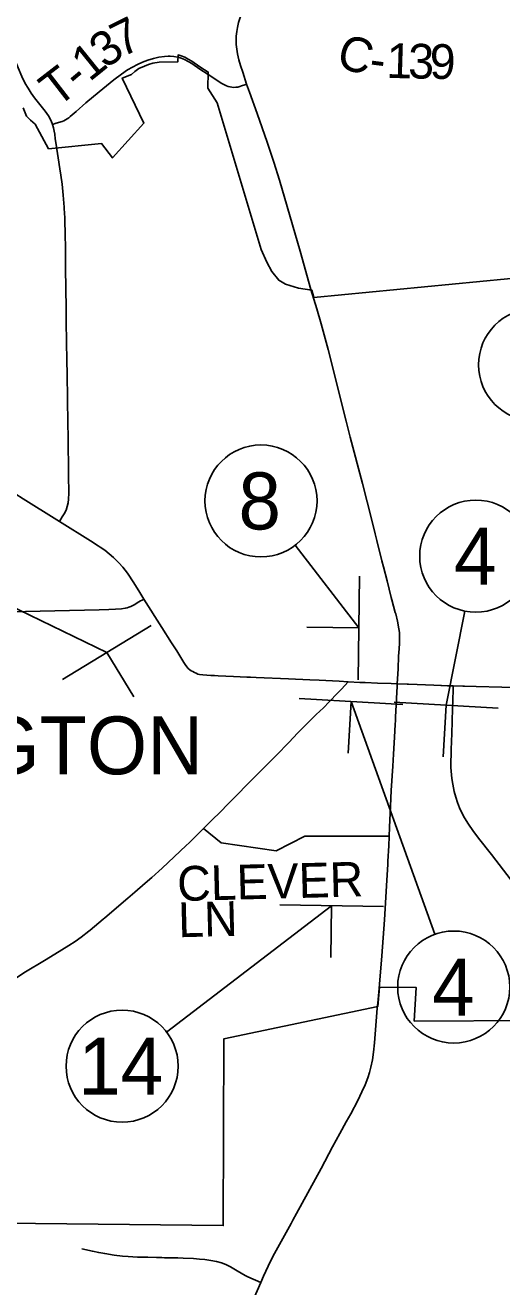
# Model space of a CAD drawing. Extents: x 40529 to 41139, y 15164 to 15584.
# Drawn here: x 40574.5 to 40597.9, y 15483.8 to 15545.7 of the extents above; entities that cross this region are included whole.
import ezdxf

# ---------------------------------------------------------------- set-up
doc = ezdxf.new("R2010")
doc.units = 0
for name, color, linetype in [('Default', 7, 'Continuous'), ('GM_X_Corporation', 7, 'Continuous'), ('GM_X_Corporation_Text', 7, 'Continuous'), ('GM_X_County_Road', 7, 'Continuous'), ('GM_X_County_Road_Text', 7, 'Continuous'), ('GM_X_State_Route', 7, 'Continuous'), ('GM_X_Township_Road', 7, 'Continuous'), ('GM_X_Township_Road_Text', 7, 'Continuous'), ('GM_X_US_Route', 7, 'Continuous'), ('SH_Data', 7, 'Continuous'), ('SH_Text', 7, 'Continuous')]:
    doc.layers.add(name, color=color, linetype=linetype)

msp = doc.modelspace()

# ---------------------------------------------------------------- linework, layer by layer
at = {"layer": 'Default'}
for p, q in [((40590.846, 15513.587), (40590.911, 15518.682)), ((40580.694, 15516.247), (40576.336, 15513.605)), ((40590.878, 15516.135), (40588.331, 15516.167)), ((40578.515, 15514.926), (40579.836, 15512.747)), ((40593.047, 15512.379), (40587.96, 15512.674)), ((40590.503, 15512.527), (40590.356, 15509.983)), ((40597.711, 15512.194), (40592.623, 15512.489)), ((40595.167, 15512.342), (40595.019, 15509.798)), ((40592.094, 15502.449), (40586.998, 15502.53)), ((40589.546, 15502.489), (40589.505, 15499.942))]:
    msp.add_line(p, q, dxfattribs=at)
at = {"layer": 'GM_X_Corporation'}
for points in [[(40574.415, 15541.668), (40574.579, 15541.261), (40574.764, 15541.07), (40574.995, 15540.877), (40575.659, 15539.66), (40578.26, 15539.918), (40578.801, 15539.217), (40580.335, 15540.921), (40579.273, 15543.132), (40579.735, 15543.317), (40579.897, 15543.465), (40580.094, 15543.602), (40580.369, 15543.72), (40580.566, 15543.794), (40580.777, 15543.873), (40581.091, 15543.917), (40582.008, 15543.936), (40582.017, 15544.274), (40582.17, 15544.232), (40582.342, 15544.167), (40582.514, 15544.071), (40582.692, 15543.967), (40583.087, 15543.69), (40583.492, 15543.427), (40583.468, 15542.633), (40583.924, 15541.916), (40586.096, 15534.723), (40586.369, 15534.1), (40586.605, 15533.632), (40586.952, 15533.206), (40587.283, 15533.011), (40587.925, 15532.817), (40588.569, 15532.721), (40588.667, 15532.351), (40599.537, 15533.4)], [(40599.428, 15496.849), (40593.604, 15496.829), (40593.696, 15498.468), (40591.901, 15498.496), (40591.807, 15497.538), (40584.261, 15495.958), (40584.228, 15486.786), (40568.876, 15486.953)]]:
    msp.add_lwpolyline(points, dxfattribs=at)
at = {"layer": 'GM_X_County_Road'}
for p, q in [((40588.817, 15531.798), (40588.534, 15532.758)), ((40592.672, 15516.895), (40592.505, 15517.511))]:
    msp.add_line(p, q, dxfattribs=at)
for points in [[(40585.377, 15542.831), (40585.183, 15543.422), (40585.071, 15543.759), (40584.995, 15544.028), (40584.931, 15544.321), (40584.89, 15544.561), (40584.868, 15544.786), (40584.862, 15544.992), (40584.87, 15545.198), (40584.893, 15545.423), (40584.927, 15545.626), (40584.98, 15545.864), (40585.038, 15546.062), (40585.111, 15546.256), (40585.213, 15546.477), (40585.329, 15546.692), (40585.456, 15546.899), (40585.55, 15547.013)], [(40575.847, 15540.859), (40575.793, 15541.042), (40575.658, 15541.286), (40575.497, 15541.512), (40574.975, 15542.169), (40574.81, 15542.396), (40574.656, 15542.631), (40574.516, 15542.875), (40574.35, 15543.21), (40574.164, 15543.639), (40573.891, 15544.313)], [(40588.534, 15532.758), (40587.999, 15534.631), (40586.987, 15538.122), (40586.712, 15539.012), (40586.389, 15539.985), (40585.896, 15541.392), (40585.515, 15542.444), (40585.377, 15542.831)], [(40575.985, 15540.153), (40575.961, 15540.376), (40575.935, 15540.524), (40575.899, 15540.693), (40575.847, 15540.859)], [(40576.262, 15538.368), (40576.21, 15538.673), (40576.012, 15539.975), (40575.985, 15540.153)], [(40576.422, 15536.792), (40576.37, 15537.387), (40576.321, 15537.93), (40576.262, 15538.368)], [(40576.492, 15534.911), (40576.469, 15535.338), (40576.45, 15536.27), (40576.427, 15536.736), (40576.422, 15536.792)], [(40576.502, 15533.035), (40576.497, 15533.565), (40576.492, 15534.911)], [(40576.525, 15531.174), (40576.516, 15531.606), (40576.502, 15533.035)], [(40590.263, 15526.283), (40589.369, 15529.809), (40589.032, 15531.068), (40588.817, 15531.798)], [(40576.556, 15529.237), (40576.545, 15530.208), (40576.526, 15531.131), (40576.525, 15531.174)], [(40576.587, 15527.357), (40576.564, 15528.623), (40576.556, 15529.237)], [(40576.617, 15525.487), (40576.607, 15526.198), (40576.587, 15527.357)], [(40591.685, 15520.756), (40591.512, 15521.419), (40591.057, 15523.224), (40590.461, 15525.502), (40590.263, 15526.283)], [(40576.641, 15523.639), (40576.641, 15523.68), (40576.617, 15525.487)], [(40576.192, 15521.358), (40576.332, 15521.582), (40576.432, 15521.743), (40576.514, 15521.913), (40576.577, 15522.092), (40576.618, 15522.277), (40576.637, 15522.464), (40576.646, 15522.746), (40576.641, 15523.639)], [(40592.089, 15519.136), (40592.012, 15519.432), (40591.771, 15520.428), (40591.685, 15520.756)], [(40592.505, 15517.511), (40592.474, 15517.629), (40592.268, 15518.44), (40592.089, 15519.136)], [(40578.62, 15517.04), (40578.949, 15517.053), (40579.231, 15517.071), (40579.417, 15517.101), (40579.508, 15517.124), (40579.598, 15517.152), (40579.687, 15517.187), (40579.855, 15517.271), (40580.095, 15517.416), (40580.173, 15517.458), (40580.253, 15517.5), (40580.335, 15517.551)], [(40570.739, 15516.864), (40573.064, 15516.906), (40575.97, 15516.978), (40578.142, 15517.022), (40578.62, 15517.04)], [(40592.854, 15515.101), (40592.871, 15515.392), (40592.881, 15515.659), (40592.871, 15515.913), (40592.848, 15516.096), (40592.78, 15516.459), (40592.693, 15516.819), (40592.672, 15516.895)], [(40592.764, 15513.39), (40592.804, 15514.123), (40592.834, 15514.751), (40592.854, 15515.101)]]:
    msp.add_lwpolyline(points, dxfattribs=at)
at = {"layer": 'GM_X_State_Route'}
for p, q in [((40590.358, 15513.484), (40590.925, 15513.461)), ((40593.74, 15513.352), (40594.564, 15513.316)), ((40595.331, 15513.289), (40595.517, 15513.285))]:
    msp.add_line(p, q, dxfattribs=at)
for points in [[(40566.122, 15527.61), (40566.736, 15527.23), (40567.182, 15526.952), (40569.187, 15525.708), (40569.837, 15525.334), (40571.873, 15524.037), (40573.14, 15523.258), (40573.997, 15522.728), (40574.407, 15522.475), (40576.063, 15521.438), (40576.192, 15521.358)], [(40576.192, 15521.358), (40577.717, 15520.41), (40578.086, 15520.171), (40578.185, 15520.107), (40578.415, 15519.947), (40578.636, 15519.774), (40578.846, 15519.588), (40579.111, 15519.324), (40579.299, 15519.116), (40579.535, 15518.827), (40579.844, 15518.341), (40580.132, 15517.87), (40580.335, 15517.551), (40581.224, 15516.154), (40581.697, 15515.407), (40581.954, 15515.004), (40582.29, 15514.441), (40582.396, 15514.286), (40582.514, 15514.145), (40582.586, 15514.083), (40582.663, 15514.03), (40582.735, 15513.992), (40582.813, 15513.948), (40582.895, 15513.905), (40582.982, 15513.861), (40583.069, 15513.847), (40583.229, 15513.827), (40583.612, 15513.795), (40583.635, 15513.794), (40583.799, 15513.79), (40583.985, 15513.781), (40584.734, 15513.752), (40585.387, 15513.722), (40585.573, 15513.712), (40585.851, 15513.702), (40587.435, 15513.632), (40588.479, 15513.586), (40588.935, 15513.571), (40589.911, 15513.513), (40590.358, 15513.484)], [(40590.925, 15513.461), (40591.195, 15513.452), (40591.79, 15513.428)], [(40591.79, 15513.428), (40592.476, 15513.401), (40592.764, 15513.39)], [(40591.882, 15498.423), (40591.901, 15498.635), (40592.012, 15500.03), (40592.141, 15501.797), (40592.247, 15503.472), (40592.299, 15504.533), (40592.306, 15504.681), (40592.346, 15505.439), (40592.39, 15506.356), (40592.434, 15507.385), (40592.474, 15508.142), (40592.545, 15509.339), (40592.583, 15509.934), (40592.635, 15510.769), (40592.67, 15511.384), (40592.68, 15511.59), (40592.688, 15511.754), (40592.759, 15513.281), (40592.764, 15513.39)], [(40592.764, 15513.39), (40593.312, 15513.37), (40593.74, 15513.352)], [(40594.564, 15513.316), (40595.238, 15513.29), (40595.331, 15513.289)], [(40595.517, 15513.285), (40596.631, 15513.262), (40597.893, 15513.227), (40598.548, 15513.205)], [(40591.788, 15497.466), (40591.807, 15497.702), (40591.882, 15498.423)], [(40587.647, 15487.052), (40587.823, 15487.38), (40589.026, 15489.584), (40589.591, 15490.651), (40589.952, 15491.3), (40590.262, 15491.871), (40590.484, 15492.277), (40590.833, 15492.93), (40591.037, 15493.347), (40591.186, 15493.69), (40591.318, 15494.04), (40591.402, 15494.305), (40591.473, 15494.57), (40591.545, 15494.928), (40591.601, 15495.295), (40591.653, 15495.758), (40591.788, 15497.466)], [(40585.105, 15481.789), (40586.07, 15483.984), (40586.203, 15484.298), (40586.427, 15484.789), (40586.662, 15485.258), (40587.559, 15486.888), (40587.647, 15487.052)]]:
    msp.add_lwpolyline(points, dxfattribs=at)
at = {"layer": 'GM_X_Township_Road'}
for points in [[(40575.847, 15540.859), (40576.032, 15540.914), (40576.321, 15541), (40576.409, 15541.036), (40576.493, 15541.079), (40576.651, 15541.183), (40576.725, 15541.242), (40577.005, 15541.492), (40577.495, 15541.921), (40578.137, 15542.46), (40578.861, 15543.045), (40579.231, 15543.326), (40579.537, 15543.535), (40579.775, 15543.678), (40580.022, 15543.807), (40580.275, 15543.918), (40580.537, 15544.013), (40580.803, 15544.092), (40581.073, 15544.155), (40581.347, 15544.197), (40581.53, 15544.211), (40581.622, 15544.211), (40581.804, 15544.195), (40581.985, 15544.161)], [(40581.985, 15544.161), (40582.009, 15544.154), (40582.162, 15544.112), (40582.333, 15544.047), (40582.505, 15543.951), (40582.683, 15543.847), (40583.077, 15543.571), (40583.482, 15543.308)], [(40583.482, 15543.308), (40583.814, 15543.092), (40584.127, 15542.886), (40584.294, 15542.796), (40584.381, 15542.758), (40584.47, 15542.726), (40584.563, 15542.701), (40584.657, 15542.685), (40584.753, 15542.678), (40584.849, 15542.681), (40584.944, 15542.693), (40585.037, 15542.716), (40585.128, 15542.749), (40585.287, 15542.801), (40585.377, 15542.831)], [(40595.454, 15511.496), (40595.459, 15511.622), (40595.51, 15513.094), (40595.517, 15513.285)], [(40598.353, 15503.75), (40597.388, 15505.009), (40596.755, 15505.814), (40596.476, 15506.183), (40596.266, 15506.489), (40596.073, 15506.806), (40595.942, 15507.051), (40595.826, 15507.304), (40595.724, 15507.563), (40595.637, 15507.827), (40595.564, 15508.095), (40595.486, 15508.458), (40595.441, 15508.733), (40595.404, 15509.102), (40595.397, 15509.287), (40595.407, 15510.219), (40595.422, 15510.502), (40595.454, 15511.496)], [(40592.369, 15505.91), (40588.238, 15505.913), (40586.833, 15505.185), (40584.127, 15505.575), (40583.262, 15506.285)], [(40577.296, 15485.648), (40577.812, 15485.528), (40578.122, 15485.458), (40578.416, 15485.406), (40578.877, 15485.338), (40579.284, 15485.29), (40579.563, 15485.264), (40580.03, 15485.238), (40580.533, 15485.229), (40580.961, 15485.217), (40581.221, 15485.211), (40581.352, 15485.208), (40582.003, 15485.197), (40582.264, 15485.188), (40582.765, 15485.161), (40583.062, 15485.139), (40583.32, 15485.112), (40583.614, 15485.072), (40583.905, 15485.017), (40584.138, 15484.958), (40584.277, 15484.91), (40584.395, 15484.86), (40584.592, 15484.759), (40584.91, 15484.57), (40585.299, 15484.335), (40585.434, 15484.267), (40586.07, 15483.984)]]:
    msp.add_lwpolyline(points, dxfattribs=at)
at = {"layer": 'GM_X_US_Route'}
for p, q in [((40590.358, 15513.484), (40590.925, 15513.461)), ((40593.74, 15513.352), (40594.564, 15513.316)), ((40595.331, 15513.289), (40595.517, 15513.285))]:
    msp.add_line(p, q, dxfattribs=at)
for points in [[(40588.581, 15511.663), (40588.794, 15511.875), (40589.141, 15512.216), (40589.423, 15512.512), (40589.844, 15512.953), (40590.032, 15513.134), (40590.358, 15513.484)], [(40590.925, 15513.461), (40591.195, 15513.452), (40591.79, 15513.428)], [(40591.79, 15513.428), (40592.476, 15513.401), (40592.764, 15513.39)], [(40592.764, 15513.39), (40593.312, 15513.37), (40593.74, 15513.352)], [(40594.564, 15513.316), (40595.238, 15513.29), (40595.331, 15513.289)], [(40595.517, 15513.285), (40596.631, 15513.262), (40597.893, 15513.227), (40598.548, 15513.205)], [(40577.631, 15501.24), (40577.704, 15501.297), (40578.34, 15501.828), (40578.419, 15501.895), (40579.552, 15502.865), (40579.889, 15503.153), (40580.402, 15503.592), (40580.721, 15503.874), (40581.239, 15504.333), (40582.415, 15505.453), (40582.552, 15505.587), (40583.19, 15506.213), (40583.72, 15506.745), (40584.048, 15507.061), (40584.505, 15507.526), (40585.805, 15508.851), (40586.99, 15510.038), (40587.3, 15510.355), (40587.445, 15510.504), (40587.893, 15510.978), (40588.09, 15511.176), (40588.581, 15511.663)], [(40575.966, 15500.115), (40576.653, 15500.531), (40576.965, 15500.734), (40577.266, 15500.952), (40577.631, 15501.24)], [(40567.855, 15493.172), (40568.753, 15494.234), (40569.122, 15494.655), (40569.147, 15494.683), (40569.426, 15494.993), (40569.944, 15495.516), (40570.782, 15496.286), (40572.08, 15497.483), (40572.43, 15497.8), (40572.78, 15498.086), (40573.096, 15498.313), (40573.713, 15498.728), (40573.905, 15498.846), (40574.101, 15498.966), (40574.522, 15499.241), (40575.457, 15499.807), (40575.966, 15500.115)]]:
    msp.add_lwpolyline(points, dxfattribs=at)
at = {"layer": 'SH_Data'}
for p, q in [((40578.515, 15514.926), (40566.148, 15520.904)), ((40590.878, 15516.135), (40587.758, 15520.189)), ((40595.167, 15512.342), (40596.083, 15516.961)), ((40590.503, 15512.527), (40594.61, 15501.087)), ((40589.546, 15502.489), (40581.451, 15496.285))]:
    msp.add_line(p, q, dxfattribs=at)
msp.add_lwpolyline([(40592.764, 15513.39), (40593.74, 15513.352), (40594.564, 15513.316), (40595.331, 15513.289), (40596.631, 15513.262), (40597.893, 15513.227), (40598.548, 15513.205)], dxfattribs=at)
at = {"layer": 'SH_Text'}
for centre in [(40599.505, 15529.056), (40586.081, 15522.369), (40596.618, 15519.658), (40595.539, 15498.499), (40579.268, 15494.613)]:
    msp.add_circle(centre, 2.75, dxfattribs=at)

# ---------------------------------------------------------------- texts
at = {"layer": 'GM_X_Corporation_Text'}
msp.add_text('LEXINGTON', height=2.8409, rotation=0.00001, dxfattribs=at).set_placement((40561.286, 15508.944))
at = {"layer": 'GM_X_County_Road_Text'}
for s, rotation, p in [('C', 343.60694, (40589.707, 15543.708)), ('1', 358.26769, (40592.216, 15543.15)), ('3', 359.09186, (40593.294, 15543.118)), ('9', 359.14965, (40594.347, 15543.101)), ('-', 352.80791, (40591.344, 15543.252))]:
    msp.add_text(s, height=1.706, rotation=rotation, dxfattribs=at).set_placement(p)
at = {"layer": 'GM_X_Township_Road_Text'}
for s, height, rotation, p in [('7', 1.706, 26.26506, (40579.238, 15544.127)), ('3', 1.706, 35.53874, (40578.453, 15543.558)), ('1', 1.706, 38.93454, (40577.663, 15542.919)), ('T', 1.706, 37.72973, (40576.071, 15541.649)), ('-', 1.706, 40.13464, (40577.139, 15542.477)), ('CLEVER', 1.7063, 1.48063, (40581.99, 15502.717)), ('LN', 1.7063, 1.48063, (40582.036, 15500.941))]:
    msp.add_text(s, height=height, rotation=rotation, dxfattribs=at).set_placement(p)
at = {"layer": 'SH_Text'}
for s, p in [('8', (40584.977, 15520.969)), ('4', (40595.554, 15518.258)), ('4', (40594.476, 15497.099)), ('14', (40577.117, 15493.213))]:
    msp.add_text(s, height=2.8, dxfattribs=at).set_placement(p)

doc.saveas('drawing.dxf')
